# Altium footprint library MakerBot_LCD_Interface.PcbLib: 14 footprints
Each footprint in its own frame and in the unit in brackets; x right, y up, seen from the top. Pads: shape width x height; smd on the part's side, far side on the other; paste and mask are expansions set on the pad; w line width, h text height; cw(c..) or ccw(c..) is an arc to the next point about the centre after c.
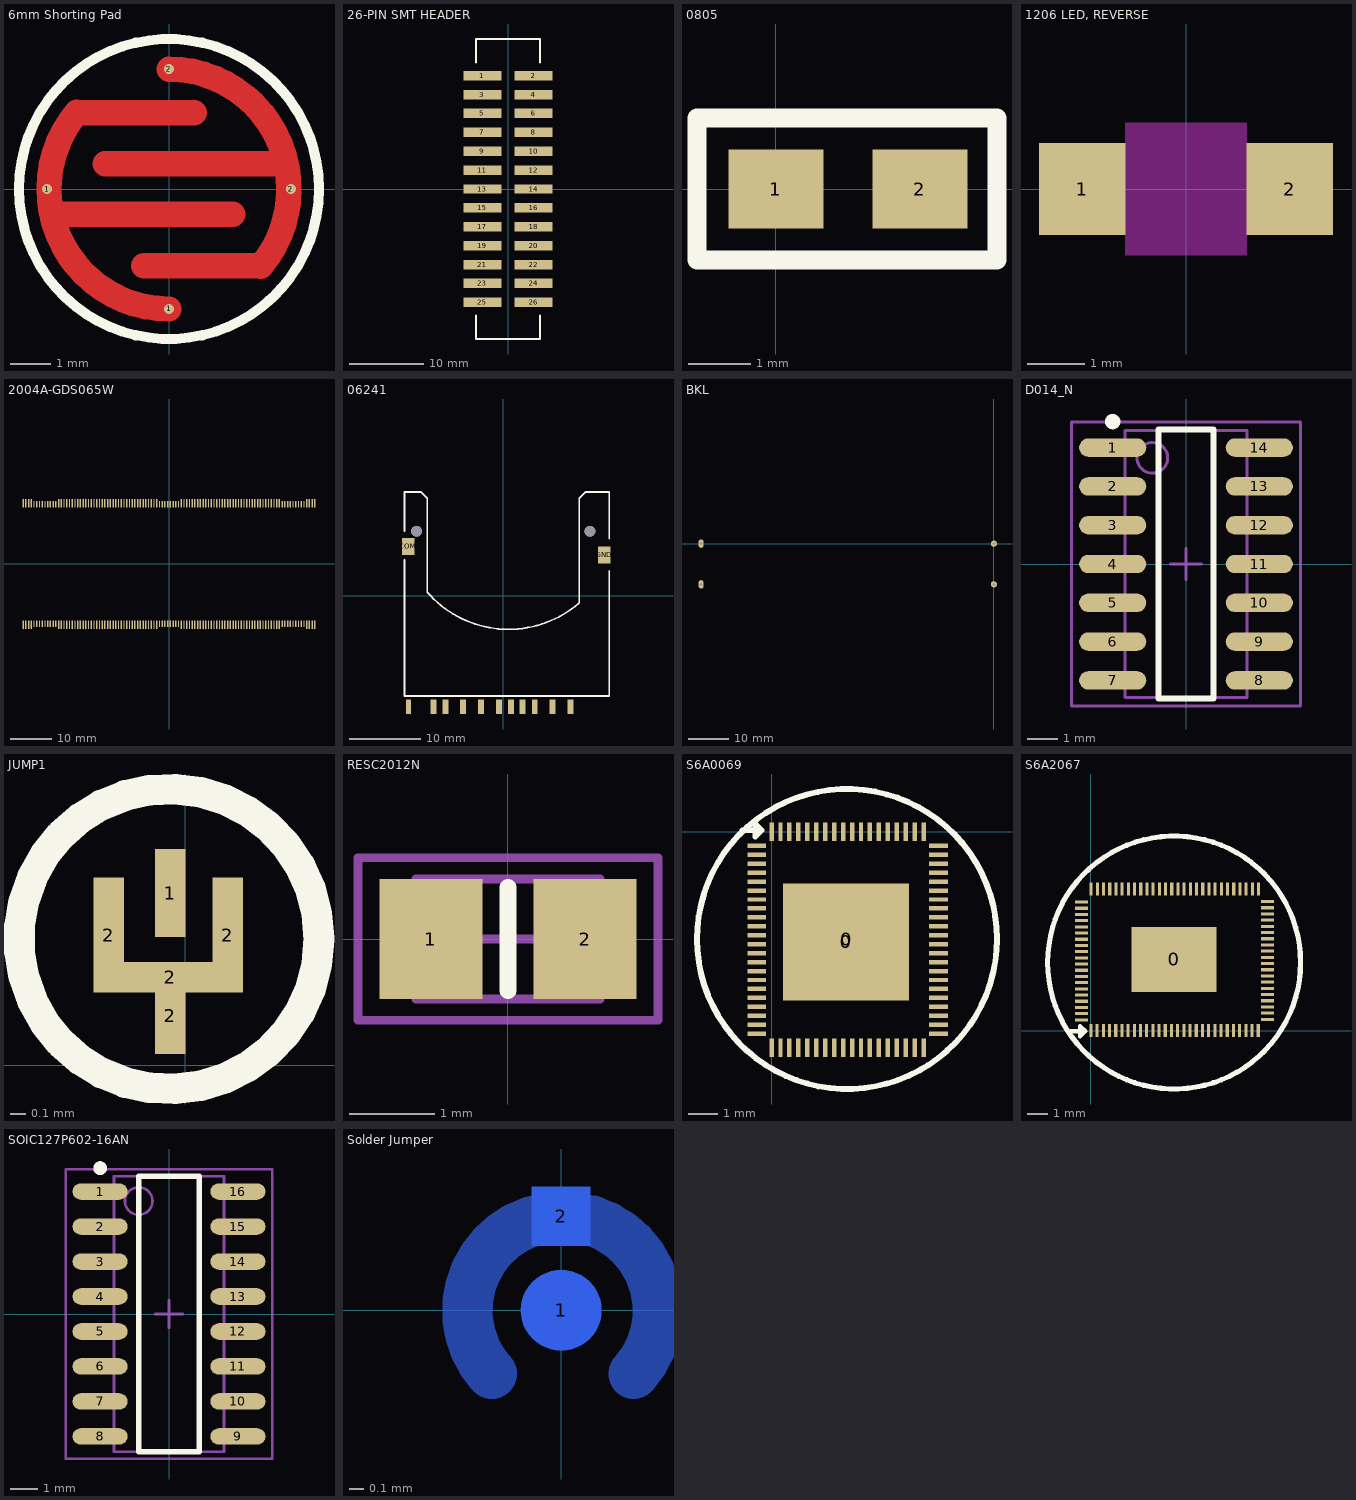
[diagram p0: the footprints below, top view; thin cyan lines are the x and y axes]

## 6mm Shorting Pad [mil] "6mm Shorting Pad for use with Silicone Button"
pads (4):
  round 10 smd: 1(-120,0) 1(0,-118.11) 2(0,118.04) 2(120,0)
Top Layer:
  lines w25: -115,-25 62.99,-25 ; -90.73,75 25,75 ; -90.73,75.61 ccw(c0,0) 0,-118.11 ; -62.99,25 115,25 ; -25,-75.58 90.44,-75.58 ; 0,118.04 cw(c-0.07,-0.07) 90.44,-75.95
Top Overlay:
  circle w10: c0,0 r147.64
Top Solder:
  circle w80: c0,0 r118.11
  lines w40: -25.44,-76 90,-76
  lines w157.48: -51,0 51,0

## 26-PIN SMT HEADER [mil] "26-PIN SMT Header,  0.1 IN., Vertical"
height 400
pads (26):
  rect 200x50 smd: 1(-135,600) 2(135,600) 3(-135,500) 4(135,500) 5(-135,400) 6(135,400) 7(-135,300) 8(135,300) 9(-135,200) 10(135,200) 11(-135,100) 12(135,100) 13(-135,0) 14(135,0) 15(-135,-100) 16(135,-100) 17(-135,-200) 18(135,-200) 19(-135,-300) 20(135,-300) 21(-135,-400) 22(135,-400) 23(-135,-500) 24(135,-500) 25(-135,-600) 26(135,-600)
Top Overlay:
  lines w10: -169,-670 -169,-794 169,-794 169,-670 ; -169,670 -169,794 169,794 169,670
3D body: height 400, standoff 3, extent -169,-794 169,794

## 0805 [mil]
pads (2):
  rect 60x50 smd: 1(0,0) 2(91.18,0)
Top Overlay:
  lines w12: -50,-45 140,-45 140,45 -50,45 -50,-45

## 1206 LED, REVERSE [mm] "1206 SMT LED, REVERSE MOUNT"
height 0.28
pads (2):
  rect 1.5x1.6 smd: 1(-1.8,0) 2(1.8,0)
Keep-Out Layer:
  board cut-out: -1.05,1.15 1.05,1.15 1.05,-1.15 -1.05,-1.15
  region: -1.05,1.15 1.05,1.15 1.05,-1.15 -1.05,-1.15

## 2004A-GDS065W [mm]
pads (216):
  rect 0.33x2 smd: 1(35.31,-14.7) 2(34.65,-14.7) 3(33.99,-14.7) 4(33.33,-14.7) 9(-35.31,-14.7) 10(35.31,14.7) 11(34.65,14.7) 12(33.99,14.7) 13(33.33,14.7) 23(26.73,14.7) 24(26.07,14.7) 25(25.41,14.7) 26(24.75,14.7) 27(24.09,14.7) 28(23.43,14.7) 29(22.77,14.7) 30(22.11,14.7) 31(21.45,14.7) 32(20.79,14.7) 33(20.13,14.7) 34(19.47,14.7) 35(18.81,14.7) 36(18.15,14.7) 37(17.49,14.7) 38(16.83,14.7) 39(16.17,14.7) 40(15.51,14.7) 41(14.85,14.7) 42(14.19,14.7) 43(13.53,14.7) 44(12.87,14.7) 45(12.21,14.7) 46(11.55,14.7) 47(10.89,14.7) 48(10.23,14.7) 49(9.57,14.7) 50(8.91,14.7) 51(8.25,14.7) 52(7.59,14.7) 53(6.93,14.7) 54(6.27,14.7) 55(5.61,14.7) 56(4.95,14.7) 57(4.29,14.7) 58(3.63,14.7) 59(2.97,14.7) 68(-2.97,14.7) 69(-3.63,14.7) 70(-4.29,14.7) 71(-4.95,14.7) 72(-5.61,14.7) 73(-6.27,14.7) 74(-6.93,14.7) 75(-7.59,14.7) 76(-8.25,14.7) 77(-8.91,14.7) 78(-9.57,14.7) 79(-10.23,14.7) 80(-10.89,14.7) 81(-11.55,14.7) 82(-12.21,14.7) 83(-12.87,14.7) 84(-13.53,14.7) 85(-14.19,14.7) 86(-14.85,14.7) 87(-15.51,14.7) 88(-16.17,14.7) 89(-16.83,14.7) 90(-17.49,14.7) 91(-18.15,14.7) 92(-18.81,14.7) 93(-19.47,14.7) 94(-20.13,14.7) 95(-20.79,14.7) 96(-21.45,14.7) 97(-22.11,14.7) 98(-22.77,14.7) 99(-23.43,14.7) 100(-24.09,14.7) 101(-24.75,14.7) 102(-25.41,14.7) 103(-26.07,14.7) 104(-26.73,14.7) 113(-33.33,14.7) 114(-33.99,14.7) 115(-34.65,14.7) 116(-35.31,14.7) 118(-34.65,-14.7) 119(-33.99,-14.7) 120(-33.33,-14.7) 130(-26.73,-14.7) 131(-26.07,-14.7) 132(-25.41,-14.7) 133(-24.75,-14.7) 134(-24.09,-14.7) 135(-23.43,-14.7) 136(-22.77,-14.7) 137(-22.11,-14.7) 138(-21.45,-14.7) 139(-20.79,-14.7) 140(-20.13,-14.7) 141(-19.47,-14.7) 142(-18.81,-14.7) 143(-18.15,-14.7) 144(-17.49,-14.7) 145(-16.83,-14.7) 146(-16.17,-14.7) 147(-15.51,-14.7) 148(-14.85,-14.7) 149(-14.19,-14.7) 150(-13.53,-14.7) 151(-12.87,-14.7) 152(-12.21,-14.7) 153(-11.55,-14.7) 154(-10.89,-14.7) 155(-10.23,-14.7) 156(-9.57,-14.7) 157(-8.91,-14.7) 158(-8.25,-14.7) 159(-7.59,-14.7) 160(-6.93,-14.7) 161(-6.27,-14.7) 162(-5.61,-14.7) 163(-4.95,-14.7) 164(-4.29,-14.7) 165(-3.63,-14.7) 166(-2.97,-14.7) 175(2.97,-14.7) 176(3.63,-14.7) 177(4.29,-14.7) 178(4.95,-14.7) 179(5.61,-14.7) 180(6.27,-14.7) 181(6.93,-14.7) 182(7.59,-14.7) 183(8.25,-14.7) 184(8.91,-14.7) 185(9.57,-14.7) 186(10.23,-14.7) 187(10.89,-14.7) 188(11.55,-14.7) 189(12.21,-14.7) 190(12.87,-14.7) 191(13.53,-14.7) 192(14.19,-14.7) 193(14.85,-14.7) 194(15.51,-14.7) 195(16.17,-14.7) 196(16.83,-14.7) 197(17.49,-14.7) 198(18.15,-14.7) 199(18.81,-14.7) 200(19.47,-14.7) 201(20.13,-14.7) 202(20.79,-14.7) 203(21.45,-14.7) 204(22.11,-14.7) 205(22.77,-14.7) 206(23.43,-14.7) 207(24.09,-14.7) 208(24.75,-14.7) 209(25.41,-14.7) 210(26.07,-14.7) 211(26.73,-14.7)
  rect 0.33x1.6 smd: 5(32.67,-14.5) 6(32.01,-14.5) 7(31.35,-14.5) 8(30.69,-14.5) 14(32.67,14.5) 15(32.01,14.5) 16(31.35,14.5) 17(30.69,14.5) 18(30.03,14.5) 19(29.37,14.5) 20(28.71,14.5) 21(28.05,14.5) 22(27.39,14.5) 60(2.31,14.5) 61(1.65,14.5) 62(0.99,14.5) 63(0.33,14.5) 64(-0.33,14.5) 65(-0.99,14.5) 66(-1.65,14.5) 67(-2.31,14.5) 105(-27.39,14.5) 106(-28.05,14.5) 107(-28.71,14.5) 108(-29.37,14.5) 109(-30.69,14.5) 110(-31.35,14.5) 111(-32.01,14.5) 112(-32.67,14.5) 117(-30.03,14.5) 121(-32.67,-14.5) 122(-32.01,-14.5) 123(-31.35,-14.5) 124(-30.69,-14.5) 125(-30.03,-14.5) 126(-29.37,-14.5) 127(-28.71,-14.5) 128(-28.05,-14.5) 129(-27.39,-14.5) 167(-2.31,-14.5) 168(-1.65,-14.5) 169(-0.99,-14.5) 170(-0.33,-14.5) 171(0.33,-14.5) 172(0.99,-14.5) 173(1.65,-14.5) 174(2.31,-14.5) 212(27.39,-14.5) 213(28.05,-14.5) 214(28.71,-14.5) 215(29.37,-14.5) 216(30.03,-14.5)

## 06241 [mm] "SD Card Slot, SMT, Push In / Push Out, Reverse Type"
height 2.85
pads (15):
  rect 0.8x2 smd: 1(6.88,-15.5) 2(4.38,-15.5) 3(1.08,-15.5) 4(-0.59,-15.5) 5(-3.12,-15.5) 6(-5.62,-15.5) 7(-8.05,-15.5) 8(-9.75,-15.5) 9(9.38,-15.5) CD(2.68,-15.5)
  rect 1.7x2.4 smd: COM(-13.25,6.9)
  rect 1.8x2.4 smd: GND(14.1,5.7)
  rect 0.7x2 smd: WP(-13.24,-15.5)
  round 1.5 hole 1.5 unplated: ""(-12.1,9) ""(12.1,9)
Top Overlay:
  lines w0.254: -13.8,5 -13.8,-14 14.8,-14 14.8,3.5 ; -13.8,9 -13.8,14.5 -11.5,14.5 -10.6,13.6 -10.6,0.5 ccw(c0.75,10.35) 10.6,-1 10.6,13.6 11.5,14.5 14.8,14.5 14.8,8
3D body: height 2.85, standoff 0, extent -13.8,-14 14.8,14.5

## BKL [mil] "2004A LCD Backlight"
pads (4):
  oval 50x80 hole 30: 1(-2834.65,-393.7) 2(-2834.65,0)
  round 60 hole 30: 1(0,0) 2(0,-393.7)

## D014_N [mm] "SOIC, 14-Leads, Body 8.7x3.9mm, Pitch 1.27mm, IPC Medium Density"
height 1.75
pads (14):
  oval 2.2x0.6 smd: 1(-2.4,3.81) 2(-2.4,2.54) 3(-2.4,1.27) 4(-2.4,0) 5(-2.4,-1.27) 6(-2.4,-2.54) 7(-2.4,-3.81) 8(2.4,-3.81) 9(2.4,-2.54) 10(2.4,-1.27) 11(2.4,0) 12(2.4,1.27) 13(2.4,2.54) 14(2.4,3.81)
Top Overlay:
  circle w0.25: c-2.4,4.66 r0.125
  lines w0.2: -0.9,-4.4 -0.9,4.4 0.9,4.4 0.9,-4.4 -0.9,-4.4
Mechanical 13:
  circle w0.1: c-1.1,3.475 r0.5
  lines w0.1: -2,-4.375 -2,4.375 2,4.375 2,-4.375 -2,-4.375
Mechanical 15:
  lines w0.1: -0.5,0 0.5,0 ; 0,-0.5 0,0.5 ; -3.75,-4.65 -3.75,4.65 3.75,4.65 3.75,-4.65 -3.75,-4.65
3D body: height 1.75, standoff 0, extent -2,-4.375 2,4.375

## JUMP1 [mil]
pads (5):
  rect 8x23 smd: 1(-4,45)
  rect 8x30 smd: 2(-20,34) 2(11,34)
  rect 8x20 smd: 2(-4,13)
  rect 38x8 smd: 2(-4,23)
Top Overlay:
  circle w8: c-4.29,33 r39.15

## RESC2012N [mm] "Chip Resistor, Body 2.0x1.2mm, IPC Medium Density"
height 0.7
pads (2):
  rect 1.2x1.4 smd: 1(-0.9,0) 2(0.9,0)
Top Overlay:
  lines w0.2: 0,-0.6 0,0.6
Mechanical 13:
  lines w0.1: -1.075,-0.7 1.075,-0.7 1.075,0.7 -1.075,0.7 -1.075,-0.7
Mechanical 15:
  lines w0.1: -0.5,0 0.5,0 ; 0,-0.5 0,0.5 ; -1.75,-0.95 1.75,-0.95 1.75,0.95 -1.75,0.95 -1.75,-0.95
3D body: height 0.7, standoff 0, extent -1.075,-0.7 1.075,0.7

## S6A0069 [mil]
pads (82):
  rect 169.29x157.48 smd: 0(100,-148)
  round 375 on Top Solder: 0(101,-144)
  rect 6x25 smd: 1(0,0) 24(0,-290) 25(12,-290) 26(24,-290) 27(36,-290) 28(48,-290) 29(60,-290) 30(72,-290) 31(84,-290) 32(96,-290) 33(108,-290) 34(120,-290) 35(132,-290) 36(144,-290) 37(156,-290) 38(168,-290) 39(180,-290) 40(192,-290) 41(204,-290) 64(204,0) 65(192,0) 66(180,0) 67(168,0) 68(156,0) 69(144,0) 70(132,0) 71(120,0) 72(108,0) 73(96,0) 74(84,0) 75(72,0) 76(60,0) 77(48,0) 78(36,0) 79(24,0) 80(12,0)
  rect 25x6 smd: 2(-20,-19) 3(-20,-31) 4(-20,-43) 5(-20,-55) 6(-20,-67) 7(-20,-79) 8(-20,-91) 9(-20,-103) 10(-20,-115) 11(-20,-127) 12(-20,-139) 13(-20,-151) 14(-20,-163) 15(-20,-175) 16(-20,-187) 17(-20,-199) 18(-20,-211) 19(-20,-223) 20(-20,-235) 21(-20,-247) 22(-20,-259) 23(-20,-271) 42(224,-271) 43(224,-259) 44(224,-247) 45(224,-235) 46(224,-223) 47(224,-211) 48(224,-199) 49(224,-187) 50(224,-175) 51(224,-163) 52(224,-151) 53(224,-139) 54(224,-127) 55(224,-115) 56(224,-103) 57(224,-91) 58(224,-79) 59(224,-67) 60(224,-55) 61(224,-43) 62(224,-31) 63(224,-19)
Top Overlay:
  lines w7: -39.81,1.94 -12.81,1.94 ; -12.81,1.94 -21.81,10.94 -21.81,-7.06 -12.81,1.94
  lines w8: 302.47,-144 cw(c101.22,-144) 302.47,-143.46

## S6A2067 [mil]
pads (97):
  rect 164x126 smd: 0(161,138)
  rect 6x25 smd: 1(0,0) 2(12,0) 3(24,0) 4(36,0) 5(48,0) 6(60,0) 7(72,0) 8(84,0) 9(96,0) 10(108,0) 11(120,0) 12(132,0) 13(144,0) 14(156,0) 15(168,0) 16(180,0) 17(192,0) 18(204,0) 19(216,0) 20(228,0) 21(240,0) 22(252,0) 23(264,0) 24(276,0) 25(288,0) 26(300,0) 27(312,0) 28(324,0) 49(324.5,274.15) 50(312.5,274.15) 51(300.5,274.15) 52(288.5,274.15) 53(276.5,274.15) 54(264.5,274.15) 55(252.5,274.15) 56(240.5,274.15) 57(228.5,274.15) 58(216.5,274.15) 59(204.5,274.15) 60(192.5,274.15) 61(180.5,274.15) 62(168.5,274.15) 63(156.5,274.15) 64(144.5,274.15) 65(132.5,274.15) 66(120.5,274.15) 67(108.5,274.15) 68(96.5,274.15) 69(84.5,274.15) 70(72.5,274.15) 71(60.5,274.15) 72(48.5,274.15) 73(36.5,274.15) 74(24.5,274.15) 75(12.5,274.15) 76(0.5,274.15)
  rect 25x6 smd: 29(342,22) 30(342,34) 31(342,46) 32(342,58) 33(342,70) 34(342,82) 35(342,94) 36(342,106) 37(342,118) 38(342,130) 39(342,142) 40(342,154) 41(342,166) 42(342,178) 43(342,190) 44(342,202) 45(342,214) 46(342,226) 47(342,238) 48(342,250) 77(-18,249) 78(-18,237) 79(-18,225) 80(-18,213) 81(-18,201) 82(-18,189) 83(-18,177) 84(-18,165) 85(-18,153) 86(-18,141) 87(-18,129) 88(-18,117) 89(-18,105) 90(-18,93) 91(-18,81) 92(-18,69) 93(-18,57) 94(-18,45) 95(-18,33) 96(-18,21)
Top Overlay:
  circle w10: c161.1,132 r244.9
  lines w8: -39,-1 -21,-1 ; -17,-2 -17,0 ; -21,-11 -11,-1 -21,9 -21,-11

## SOIC127P602-16AN [mm] "SOIC, 16-Leads, Body 9.9x3.9mm, Pitch 1.27mm, IPC Medium Density"
height 1.73
pads (16):
  oval 2x0.6 smd: 1(-2.5,4.445) 2(-2.5,3.175) 3(-2.5,1.905) 4(-2.5,0.635) 5(-2.5,-0.635) 6(-2.5,-1.905) 7(-2.5,-3.175) 8(-2.5,-4.445) 9(2.5,-4.445) 10(2.5,-3.175) 11(2.5,-1.905) 12(2.5,-0.635) 13(2.5,0.635) 14(2.5,1.905) 15(2.5,3.175) 16(2.5,4.445)
Top Overlay:
  circle w0.25: c-2.5,5.295 r0.125
  lines w0.2: -1.1,-5 1.1,-5 1.1,5 -1.1,5 -1.1,-5
Mechanical 13:
  circle w0.1: c-1.1,4.1 r0.5
  lines w0.1: -2,-5 2,-5 2,5 -2,5 -2,-5
Mechanical 15:
  lines w0.1: -0.5,0 0.5,0 ; 0,-0.5 0,0.5 ; -3.75,-5.25 3.75,-5.25 3.75,5.25 -3.75,5.25 -3.75,-5.25
3D body: height 1.73, standoff 0, extent -2,-5 2,5

## Solder Jumper [mil]
pads (2):
  round 22 smd far side: 1(0,0)
  rect 16x16 smd far side: 2(0,25.68)
Bottom Layer:
  lines w13.78: -18.98,-17.38 cw(c0.03,-0.1) 0,25.59 cw(c0.76,-0.1) 19.77,-17.38
Top Overlay:
